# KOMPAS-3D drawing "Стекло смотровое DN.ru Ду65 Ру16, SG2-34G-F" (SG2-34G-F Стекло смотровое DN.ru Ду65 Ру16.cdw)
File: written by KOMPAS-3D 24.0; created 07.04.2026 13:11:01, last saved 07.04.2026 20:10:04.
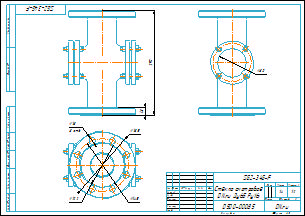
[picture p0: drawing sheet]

Document properties: Автор: Main; Форматы листов документа: A3; Полное имя файла: SG2-34G-F Стекло смотровое DN.ru Ду65 Ру16.m3d; Масса: 14; Наименование: Стекло смотровое DN.ru Ду65 Ру16; Количество листов документа: 1; Примечание: D500-00085

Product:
- Body: Тело 1  | qty 1
    Масса: 13.01185
- Part/product: Стекло смотровое DN.ru Ду65 Ру16  | designation SG2-34G-F
    Масса: 14
    Раздел спецификации: Прочие изделия
    Примечание: D500-00085

Views: Вид 1, Снизу, Проекционный вид 2
Referenced files in D:\DN.ru Аутсерс\Стекло смотровое DN.ru\Стекло смотровое DN.ru SG2-34G-F тип В ГОСТ 21836-2021 Ду100 Ру16, углеродистая сталь, фланцевое\: SG2-34G-F тип В Стекло смотровое DN.ru Ду100 Ру16.m3d, SG2-34G-F тип ВСтекло смотровое DN.ru Ду100 Ру16.cdw
Referenced files in D:\DN.ru Аутсерс\Стекло смотровое DN.ru\SG2-34G-F Стекло смотровое DN.ru Ду65 Ру16\: SG2-34G-F Стекло смотровое DN.ru Ду65 Ру16.m3d
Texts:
  SG2-34G-F
  Стекло смотровое
  DN.ru Ду65 Ру16
  Стекло смотровое DN.ru Ду65 Ру16
  SG2-34G-F Стекло смотровое DN.ru Ду65 Ру16
Dimensions and other numbers on the sheet: 0; 3; 2; 4; 290; 18; 8 отв.; 185; 145; 122; 1:2; 1; 14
